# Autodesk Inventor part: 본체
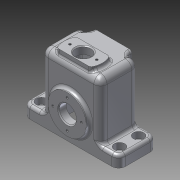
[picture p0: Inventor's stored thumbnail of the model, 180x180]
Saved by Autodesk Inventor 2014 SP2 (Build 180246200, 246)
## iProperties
Created: 2023-12
Part Number: 본체
Material: 알루미늄 6061
Document SubType Name: Modeling
Designer: 거성
Density: 2.71 g/cm^3
Appearance: 알루미늄 - 평지
Mass: 219.911 g
Surface Area: 358.721 cm^2
Volume: 81.1479 cm^3
Author: 거성
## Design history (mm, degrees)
sketch "스케치1"
  geometry: L1 (36, 20)-(-36, 20); L2 (-36, 20)-(-36, -20); L3 (-36, -20)-(36, -20); L4 (36, -20)-(36, 20); L5 (36, 20)-(-36, -20); L6 (-36, 20)-(36, -20); 1 further point
  constraints: 12 end point, 2 midpoint, 2 parallel, 1 horizontal, 1 perpendicular
  dimensions: "d0" = 72 distance of L3.end L2.end; "d1" = 40 distance of L2.end L1.end
extrude "돌출1" new body sketch "스케치1" stored distance "d2" = 62; taper "d3" = 0 deg
fillet "모깎기1" dims "d5" = 7
fillet "모깎기2" dims "d6" = 7
feature "쉘1" dims "d4" = 4
sketch "스케치2"
  geometry: L1 (0, 0)-(48, 0) reference; C1 r 20 at (24, 28); 1 further point
  constraints: 1 centre point, 1 vertical alignment
  dimensions: "d7" = 40 diameter of C1; "d8" = 28 distance from line of C1.centre L1
extrude "돌출2" join sketch "스케치2" distance "d9" = 4; taper "d10" = 0 deg
sketch "스케치3"
  geometry: C1 r 20 at (0, 0) reference; C2 r 9 at (0, 0); 1 further point
  constraints: 1 centre point, 1 coincident
  dimensions: "d11" = 18 diameter of C2
extrude "돌출3" cut sketch "스케치3" distance "d12" = 8; taper "d13" = 0 deg
sketch "스케치4"
  geometry: L1 (48, 0)-(0, 0) reference; C1 r 12 at (24, 28); 1 further point
  constraints: 1 centre point, 1 vertical alignment
  dimensions: "d14" = 24 diameter of C1; "d15" = 28 distance from line of L1 C1.centre
extrude "돌출4" join sketch "스케치4" distance "d16" = 4; taper "d17" = 0 deg
sketch "스케치7" dims "d21" = 30
  geometry: L1 (0, 0)-(0, 15); C1 r 20 at (0, 0) reference; 1 further point
  constraints: 2 end point, 1 coincident, 1 vertical, 1 vertical alignment, 2 other
hole "구멍1" sketch "스케치7" at (0, 15) diameter "d22" = 2.459; stored, may be unused: countersink angle "d26" = 90 deg, drill point angle "d28" = 118 deg; dims "d23" = 8, "d24" = 4, "d25" = 2, "d27" = 8
node "작업 평면2"
sketch "스케치12"
  geometry: L1 (-20, 36)-(20, 36); L2 (20, 36)-(20, 12); L3 (20, 12)-(-20, 12); L4 (-20, 12)-(-20, 36); L5 (-20, 36)-(20, 12); L6 (20, 36)-(-20, 12); L7 (24, 36)-(-24, 36) reference; 4 further points
  constraints: 12 end point, 5 midpoint, 2 parallel, 1 horizontal, 1 perpendicular, 1 vertical alignment
  dimensions: "d42" = 40 distance of L2.end L3.end; "d43" = 24 distance of L1.end L2.end
extrude "돌출7" join sketch "스케치12" stored distance "d44" = 8; taper "d45" = 0 deg
sketch "스케치13"
  geometry: L1 (-20, 36)-(20, 36) reference; 3 further points
  constraints: 1 horizontal alignment
  dimensions: "d46" = 28 distance of point (14, 30) point (-14, 30); "d47" = 14 horizontal distance of point (0, 0) point (-14, 30); "d48" = 6 distance from line of point (-14, 30) L1
hole "구멍2" sketch "스케치13" at (-14, 30), (14, 30) diameter "d49" = 2.459; stored, may be unused: countersink angle "d53" = 90 deg, drill point angle "d55" = 118 deg; dims "d50" = 12, "d51" = 4, "d52" = 2, "d54" = 14
node "작업 평면3"
sketch "스케치14"
  geometry: L1 (-7, -33)-(-7, -7) reference; L2 (0, 0)-(12, 0) reference; L3 (12, 0)-(12, 4) reference; L4 (12, 4)-(23.285, 4) reference; L5 (23.285, 4)-(23.285, -4) reference; L6 (23.285, -4)-(0, -4) reference; L7 (-3, -7)-(-3, -33) reference; L8 (0, -36)-(48, -36) reference; L9 (51, -33)-(51, -7) reference; L10 (48, -4)-(24.715, -4) reference; L11 (24.715, -4)-(24.715, 4) reference; L12 (24.715, 4)-(36, 4) reference; L13 (36, 4)-(36, 0) reference; L14 (36, 0)-(48, 0) reference; L15 (55, -7)-(55, -33) reference; L16 (48, -40)-(0, -40) reference; L17 (74, -40)-(-26, -40); L18 (-26, -40)-(-26, 0); L19 (74, 0)-(74, -40); L20 (74, -40)-(-26, 0); L21 (-26, -40)-(74, 0); L22 (-26, 0)-(12, 0); L23 (36, 0)-(74, 0); L24 (-7, -33)-(-7, -7) reference; L25 (55, -7)-(55, -33) reference; A1 r 7 centre (0, -33) between (-7, -33) and (0, -40) reference; A2 r 7 centre (0, -7) between (0, 0) and (-7, -7) reference; A3 r 3 centre (0, -7) between (0, -4) and (-3, -7) reference; A4 r 3 centre (0, -33) between (-3, -33) and (0, -36) reference; A5 r 3 centre (48, -33) between (48, -36) and (51, -33) reference; A6 r 3 centre (48, -7) between (51, -7) and (48, -4) reference; A7 r 7 centre (48, -7) between (55, -7) and (48, 0) reference; A8 r 7 centre (48, -33) between (48, -40) and (55, -33) reference; A9 r 7 centre (0, -7) between (0, 0) and (-7, -7) reference; A10 r 7 centre (0, -33) between (-7, -33) and (0, -40) reference; A11 r 7 centre (48, -33) between (48, -40) and (55, -33) reference; A12 r 7 centre (48, -7) between (55, -7) and (48, 0) reference; 1 further point
  constraints: 16 end point, 3 parallel, 2 midpoint, 1 horizontal, 1 perpendicular, 1 point on line
  dimensions: "d57" = 100 distance between parallel lines of L19 L18
extrude "돌출8" join sketch "스케치14" distance "d58" = 12; taper "d59" = 0 deg
sketch "스케치15"
  geometry: L1 (48, 36)-(0, 36) reference; L2 (-3, 33)-(-3, 7) reference; L3 (0, 4)-(23.285, 4) reference; L4 (23.285, 4)-(23.285, -4) reference; L5 (23.285, -4)-(12, -4) reference; L6 (12, -4)-(12, 0) reference; L7 (12, 0)-(0, 0) reference; L8 (-7, 7)-(-7, 33) reference; L9 (-26, 40)-(0, 40) reference; L10 (-26, 0)-(-26, 40) reference; L11 (0, 0)-(-26, 0) reference; L12 (51, 7)-(51, 33) reference; L13 (24.715, 4)-(48, 4) reference; L14 (24.715, -4)-(24.715, 4) reference; L15 (36, -4)-(24.715, -4) reference; L16 (36, 0)-(36, -4) reference; L17 (48, 0)-(36, 0) reference; L18 (55, 33)-(55, 7) reference; L19 (48, 40)-(74, 40) reference; L20 (74, 40)-(74, 0) reference; L21 (74, 0)-(48, 0) reference; L22 (0, 40)-(48, 40) reference; A1 r 3 centre (0, 33) between (0, 36) and (-3, 33) reference; A2 r 3 centre (0, 7) between (-3, 7) and (0, 4) reference; A3 r 7 centre (0, 7) between (-7, 7) and (0, 0) reference; A4 r 7 centre (0, 33) between (0, 40) and (-7, 33) reference; A5 r 3 centre (48, 33) between (51, 33) and (48, 36) reference; A6 r 3 centre (48, 7) between (48, 4) and (51, 7) reference; A7 r 7 centre (48, 7) between (48, 0) and (55, 7) reference; A8 r 7 centre (48, 33) between (55, 33) and (48, 40) reference; 5 further points
  constraints: 2 horizontal alignment, 2 vertical alignment
  dimensions: "d60" = 82 distance of point (-17, 30) point (65, 30); "d61" = 41 horizontal distance of point (24, 20) point (-17, 30); "d62" = 10 distance from line of point (-17, 10) L11; "d63" = 20 distance of point (-17, 10) point (-17, 30)
hole "구멍3" sketch "스케치15" at (65, 30), (-17, 30), (-17, 10), (65, 10) diameter "d64" = 6.6; stored, may be unused: countersink angle "d68" = 90 deg, drill point angle "d70" = 118 deg; dims "d65" = 8, "d66" = 11, "d67" = 6.6, "d69" = 12
fillet "모깎기3" dims "d71" = 7
node "작업 평면4"
sketch "스케치16"
  geometry: L1 (-57, 27)-(-29, 27); L2 (-60.321, 17)-(-25.679, 17); L3 (-25.679, 37)-(-60.321, 37); L4 (-63, -4)-(-23, -4) reference; A1 r 20 centre (-43, 27) between (-60.321, 37) and (-60.321, 17); A2 r 20 centre (-43, 27) between (-25.679, 17) and (-25.679, 37); 2 further points
  constraints: 8 end point, 4 point on circle, 2 centre point, 1 coincident, 1 horizontal, 1 midpoint, 1 parallel, 1 vertical alignment
  dimensions: "d75" = 28 distance of L1.start L1.end; "d76" = 31 distance from line of point (-43, 27) L4; "d91" = 20 radius of A1; "d92" = 20 radius of A2; "d94" = 10 distance from line of L3 point (-43, 27); "d95" = 20 distance between parallel lines of L2 L3; "d96" = 10 vertical distance of L2.end point (-43, 27)
extrude "돌출9" join sketch "스케치16" stored distance "d77" = 12; taper "d78" = 0 deg
sketch "스케치17"
  geometry: L1 (25.679, -37)-(60.321, -37) reference; C1 r 8 at (43, -27); 1 further point
  constraints: 1 centre point, 1 vertical alignment
  dimensions: "d79" = 16 diameter of C1; "d97" = 10 distance from line of L1 C1.centre
extrude "돌출10" cut sketch "스케치17" stored distance "d80" = 12; taper "d81" = 0 deg
sketch "스케치18"
  geometry: 9 further points
  constraints: 2 coincident, 2 other
hole "구멍4" sketch "스케치18" at (57, -27), (29, -27) diameter "d82" = 2.459; stored, may be unused: countersink angle "d86" = 90 deg, drill point angle "d88" = 118 deg; dims "d83" = 8, "d84" = 11, "d85" = 6.6, "d87" = 12
chamfer "모따기1" distance "d98" = 1; stored, may be unused: second distance "d99" = 2, angle "d100" = 45 deg
fillet "모깎기5" dims "d101" = 3
fillet "모깎기6" dims "d102" = 3
fillet "모깎기7" dims "d103" = 3
fillet "모깎기8" dims "d104" = 3
fillet "모깎기9" dims "d105" = 3
fillet "모깎기10" dims "d106" = 3
fillet "모깎기12" dims "d108" = 3
fillet "모깎기13" dims "d109" = 3
fillet "모깎기14" dims "d110" = 3
sketch "스케치19"
  geometry: L1 (-24, 4)-(-24, -20) reference; L2 (13, -36)-(-13, -36) reference; 2 further points
  constraints: 1 other
  dimensions: "d111" = 23 distance from line of point (-1, 4) L1; "d112" = 40 distance from line of L2 point (-1, 4)
feature "엠보싱1" sketch "스케치19" dims "d113" = 0.5, "d114" = 0
sketch "스케치21"
  geometry: C1 r 12 at (0, 0) reference; C2 r 8 at (0, 0); 1 further point
  constraints: 1 centre point, 1 coincident
  dimensions: "d122" = 16 diameter of C2
extrude "돌출11" cut sketch "스케치21" distance "d123" = 8; taper "d124" = 0 deg
feature "스레드1" dims "d125" = 10, "d126" = 0
node "솔리드1"
pattern_circular "원형 패턴1" dims angle "d30" = 360 deg
node "절단 모서리 투영1"
node "절단 모서리 투영2"
other parameters: "d41" = -24, "d56" = -12, "d72" = -76
